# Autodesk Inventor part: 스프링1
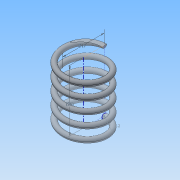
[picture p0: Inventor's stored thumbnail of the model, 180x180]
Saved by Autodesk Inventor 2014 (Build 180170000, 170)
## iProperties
Created: 2016-03
Part Number: 스프링1
Material: 일반
Document SubType Name: Modeling
Designer: net
Density: 1 g/cm^3
Appearance: 기본값
Author: net
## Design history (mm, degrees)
sketch "스케치1"
  geometry: L1 (0, 0)-(8.5, 0); L2 (8.5, 0)-(8.5, 20.5); L3 (8.5, 20.5)-(0, 20.5); L4 (0, 20.5)-(0, 0); C1 r 1 at (8.5, 0)
  constraints: 8 end point, 2 parallel, 1 centre point, 1 coincident, 1 horizontal, 1 perpendicular
  dimensions: "d0" = 20.5 distance of L3.end L1.start (derived); "d1" = 2 diameter of C1; "d2" = 17 diameter of L2 L4
feature "코일1" sketch "스케치1" pitch "d3" = 10; turns "d5" = 5; dims "d4" = 20.5 (= d0), "d6" = 0, angle "d7" = 90 deg, angle "d8" = 90 deg, "d9" = 0, "d10" = 0
sketch "스케치2"
  geometry: L1 (0, 7.5)-(0, 9.5) reference; 1 further point
  constraints: 1 vertical alignment
extrude "돌출1" cut sketch "스케치2" stored distance "d11" = 10; taper "d12" = 0 deg
node "작업 평면1"
sketch "스케치3"
  geometry: L1 (0, -2)-(0, 0) reference; 1 further point
  constraints: 1 vertical alignment
extrude "돌출2" cut sketch "스케치3" stored distance "d13" = 10; taper "d14" = 0 deg
node "솔리드1"
node "절단 모서리 투영1"
node "절단 모서리 투영2"
